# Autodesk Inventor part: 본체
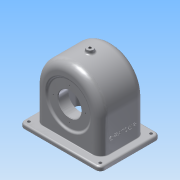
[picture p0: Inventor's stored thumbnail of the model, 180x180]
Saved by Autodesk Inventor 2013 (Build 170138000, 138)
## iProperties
Created: 2016-01
Part Number: 본체
Material: 알루미늄 6061
Document SubType Name: Modeling
Designer: Administrator
Density: 2.71 g/cm^3
Mass: 827.832 g
Surface Area: 1004.19 cm^2
Volume: 305.473 cm^3
Author: Administrator
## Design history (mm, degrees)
sketch "스케치1"
  geometry: L1 (0, 52)-(62, 52); L2 (0, 52)-(-62, 52); L3 (-70, 44)-(-70, -44); L4 (-62, -52)-(62, -52); L5 (70, -44)-(70, 44); C1 r 2.5 at (-62, 44); C2 r 2.5 at (-62, -44); C3 r 2.5 at (62, 44); C4 r 2.5 at (62, -44); A1 r 8 centre (-62, 44) between (-62, 52) and (-70, 44); A2 r 8 centre (62, 44) between (70, 44) and (62, 52); A3 r 8 centre (62, -44) between (62, -52) and (70, -44); A4 r 8 centre (-62, -44) between (-70, -44) and (-62, -52); 1 further point
  constraints: 10 end point, 8 centre point, 8 point on circle, 2 perpendicular, 2 tangent, 1 collinear
extrude "돌출1" new body sketch "스케치1" distance "d11" = 7; taper "d12" = 0 deg
sketch "스케치2"
  geometry: L1 (0, 0)-(0, 60); L2 (0, 0)-(51, 0); L3 (51, 0)-(57, 0); L4 (57, 0)-(57, 64); L5 (0, 0)-(-51, 0); L6 (-51, 0)-(-57, 0); L7 (-57, 0)-(-57, 64); A1 r 57 centre (0, 64) between (57, 64) and (-57, 64)
  constraints: 14 end point, 3 perpendicular, 2 point on circle, 1 centre point, 1 collinear, 1 point on line, 1 vertical
extrude "돌출2" join sketch "스케치2" stored distance "d24" = 77; taper "d25" = 0 deg
sketch "스케치3"
  geometry: L1 (57, 64)-(57, 7) reference; L2 (-57, 7)-(-57, 64) reference; L3 (-51, 7)-(-51, 64); L4 (51, 64)-(51, 7); L5 (-51, 7)-(-51, 0); L6 (51, 7)-(51, 0); L7 (-62, 0)-(62, 0) reference; L8 (-51, 0)-(51, 0); A1 r 57 centre (0, 64) between (57, 64) and (-57, 64) reference; A2 r 51 centre (0, 64) between (51, 64) and (-51, 64); 1 further point
  constraints: 10 end point, 2 parallel, 2 point on circle, 2 point on line, 1 centre point, 2 other
  dimensions: "d26" = 6 radial gap between concentric circles of A1 A2
extrude "돌출3" cut sketch "스케치3" stored distance "d27" = 67; taper "d28" = 0 deg
node "작업 평면1"
sketch "스케치4"
  geometry: C1 r 6 at (0, 0); 1 further point
  constraints: 1 centre point, 1 coincident
  dimensions: "d30" = 12 diameter of C1
extrude "돌출4" join sketch "스케치4" stored distance "d31" = 67; taper "d32" = 0 deg
sketch "스케치6"
  geometry: C1 r 31 at (0, -60); 1 further point
  constraints: 1 centre point
  dimensions: "d41" = 62 diameter of C1
extrude "돌출5" join sketch "스케치6" distance "d42" = 10; taper "d43" = 0 deg
sketch "스케치7"
  geometry: C1 r 31 at (0, 0) reference; C2 r 20 at (0, 0); 1 further point
  constraints: 1 centre point, 1 coincident
  dimensions: "d44" = 40 diameter of C2
extrude "돌출6" cut sketch "스케치7" distance "d45" = 20; taper "d46" = 0 deg
sketch "스케치9"
  geometry: L1 (-38.5, 60)-(-35.5, 60); L2 (-33.5, 101.426)-(-17.5, 88) reference; L3 (-33.5, 115)-(-33.5, 64) reference; L4 (-17.5, 32)-(-17.5, 88) reference; L5 (-36.714, 97.595)-(-38.5, 99.094); L6 (-35.5, 60)-(-35.5, 96.577); L7 (-38.5, 60)-(-38.5, 99.094); L8 (-36.714, 97.595)-(-35.5, 96.577); L9 (-35.5, 60)-(-9, 60); 1 further point
  constraints: 12 end point, 2 parallel, 1 collinear, 1 perpendicular
revolve "회전2" sketch "스케치9" stored, may be unused: angle "d61" = 90 deg
sketch "스케치10"
  geometry: C1 r 36.577 at (0, 0) reference; C2 r 20 at (0, 0); 1 further point
  constraints: 1 centre point, 1 coincident
  dimensions: "d62" = 40 diameter of C2
extrude "돌출7" cut sketch "스케치10" distance "d63" = 20; taper "d64" = 0 deg
sketch "스케치12"
  geometry: L1 (0, 0)-(0, -24); C1 r 31 at (0, 0) reference; 1 further point
  constraints: 2 end point, 1 coincident, 1 vertical alignment, 2 other
hole "구멍3" sketch "스케치12" at (0, -24) diameter "d77" = 2.459; stored, may be unused: countersink angle "d81" = 90 deg, drill point angle "d83" = 118 deg; dims "d78" = 6, "d79" = 4, "d80" = 2, "d82" = 8
fillet "모깎기1" dims "d87" = 14, "d88" = 9, "d89" = 3
fillet "모깎기2" dims "d90" = 3, "d98" = 1
chamfer "모따기1" distance "d91" = 1; stored, may be unused: second distance "d92" = 2, angle "d93" = 45 deg
sketch "스케치13"
  geometry: 2 further points
  constraints: 1 other
feature "엠보싱1" sketch "스케치13" dims "d96" = 0.5, "d97" = 0
sketch "스케치14"
  geometry: C1 r 6 at (0, 0) reference
hole "구멍4" sketch "스케치14" at (0, 0) diameter "d99" = 4.459; stored, may be unused: countersink angle "d103" = 90 deg, drill point angle "d105" = 118 deg; dims "d100" = 30, "d101" = 4, "d102" = 2, "d104" = 30
sketch "스케치15"
  geometry: L1 (0, 0)-(0, 60); L2 (-33.5, 60)-(-17.5, 60); L3 (-17.5, 60)-(-17.5, 88); L4 (-17.5, 88)-(-33.5, 101.426); L5 (-33.5, 106)-(-33.5, 64) reference; L6 (-33.5, 80)-(-33.5, 40) reference; L7 (-33.5, 60)-(-33.5, 101.426); L8 (-36.572, 97.476)-(-37.428, 98.195) reference; L9 (-34.249, 100.244)-(-35.105, 100.963)
  constraints: 12 end point, 1 midpoint, 1 parallel, 1 perpendicular, 1 point on line, 1 vertical
  dimensions: "d106" = 60 distance of L1.start L1.end; "d111" = 28 distance of L2.end L3.end; "d113" = 5 distance between parallel lines of L4 L8
revolve "회전3" sketch "스케치15" stored, may be unused: angle "d114" = 90 deg
sketch "스케치16"
  geometry: C1 r 20 at (0, 0) reference; C2 r 20 at (0, 0); 1 further point
  constraints: 1 centre point, 1 coincident, 1 concentric
extrude "돌출8" cut sketch "스케치16" distance "d115" = 20; taper "d116" = 0 deg
fillet "모깎기3" dims "d117" = 3
sketch "스케치17" dims "d118" = 56
  geometry: L1 (0, 0)-(0, 28); C1 r 21 at (0, 0) reference; 1 further point
  constraints: 2 end point, 1 coincident, 1 vertical, 1 vertical alignment, 2 other
hole "구멍5" sketch "스케치17" at (0, 28) diameter "d119" = 2.459; stored, may be unused: countersink angle "d123" = 90 deg, drill point angle "d125" = 118 deg; dims "d120" = 7, "d121" = 4, "d122" = 2, "d124" = 9
node "솔리드1"
pattern_circular "원형 패턴2" dims angle "d85" = 360 deg
pattern_circular "원형 패턴3" dims angle "d127" = 360 deg
other parameters: "d29" = 127
